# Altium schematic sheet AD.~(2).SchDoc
size A4
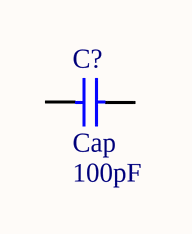
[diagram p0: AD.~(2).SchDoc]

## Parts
C?  Cap  value 100pF  [RAD-0.3]

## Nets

Not connected (* = marked no-connect by the designer): C? 1 2

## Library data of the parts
C? = Cap: Capacitor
